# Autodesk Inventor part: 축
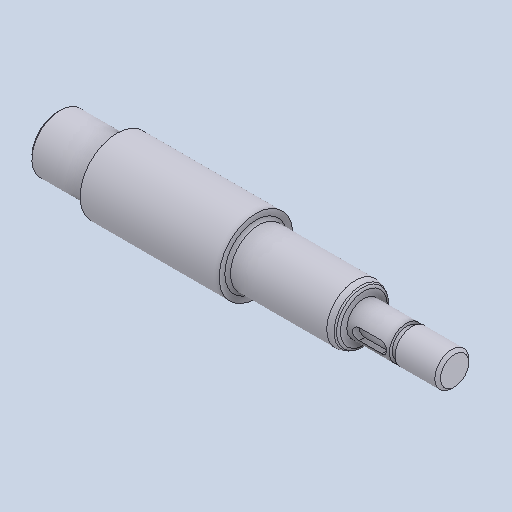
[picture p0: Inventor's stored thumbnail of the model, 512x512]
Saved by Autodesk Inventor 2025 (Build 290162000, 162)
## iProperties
Created: 2025-08
Part Number: 축
Material: 강철, 연강
Document SubType Name: Modeling
Designer: infra04
Density: 7.86 g/cm^3
Appearance: 기본값
Author: jhkim
Sending System: Autodesk Inventor 2026
Preprocessor: ST-DEVELOPER v20.1
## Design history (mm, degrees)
feature "솔리드2"
node "솔리드1"
